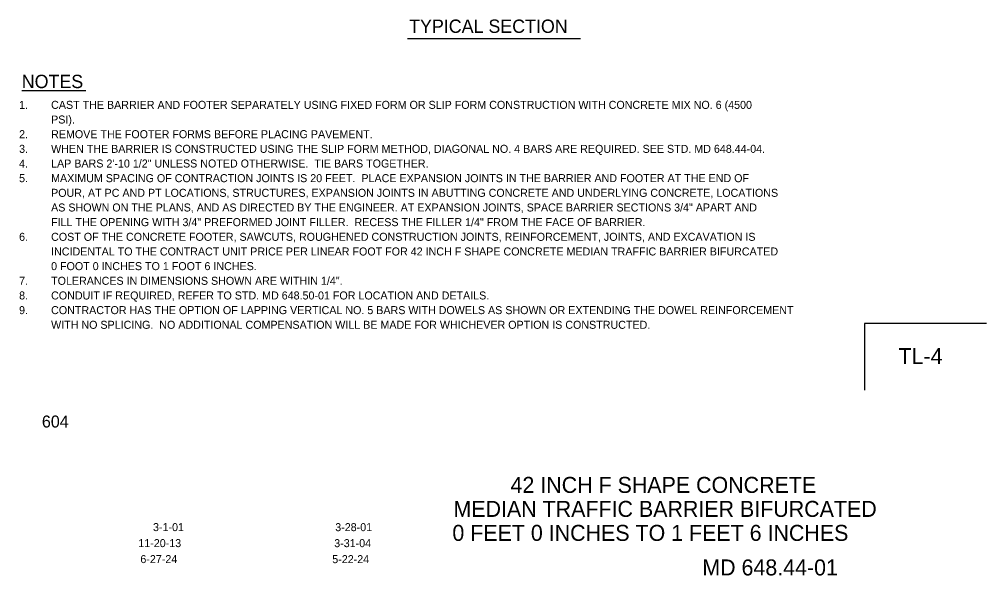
# Model space of a CAD drawing. Extents: x -26.46 to -19.21, y -3.62 to 6.25.
# Drawn here: x -26.46 to -19.21, y -3.62 to 0.55 of the extents above; entities that cross this region are included whole.
import ezdxf

# ---------------------------------------------------------------- set-up
doc = ezdxf.new("R2010")
doc.units = 0
for name, color, linetype in [('Level 1', 7, 'Continuous'), ('Level 12', 7, 'Continuous'), ('Level 13', 7, 'Continuous'), ('TTLB-TEXT', 7, 'Continuous')]:
    doc.layers.add(name, color=color, linetype=linetype)

msp = doc.modelspace()

# ---------------------------------------------------------------- linework, layer by layer
at = {"layer": 'Level 1'}
for p, q in [((-19.2061, -1.7326), (-20.1228, -1.7326)), ((-20.1228, -1.7326), (-20.1228, -2.2326))]:
    msp.add_line(p, q, dxfattribs=at)
at = {"layer": 'Level 12'}
msp.add_line((-23.5481, 0.4063), (-22.2512, 0.4063), dxfattribs=at)
at = {"layer": 'Level 13'}
msp.add_line((-26.4422, 0.0164), (-25.9619, 0.0164), dxfattribs=at)

# ---------------------------------------------------------------- texts
at = {"layer": 'Level 12'}
msp.add_text('TYPICAL SECTION', height=0.1, dxfattribs=at).set_placement((-23.5369, 0.4479))
at = {"layer": 'Level 13'}
for s, height, p in [('NOTES', 0.1, (-26.4421, 0.0334)), ('1.', 0.06, (-26.462, -0.1221)), ('CAST THE BARRIER AND FOOTER SEPARATELY USING FIXED FORM OR SLIP FORM CONSTRUCTION WITH CONCRETE MIX NO. 6 (4500 ', 0.06, (-26.222, -0.1221)), ('PSI).', 0.06, (-26.222, -0.2321)), ('2.', 0.06, (-26.462, -0.3421)), ('REMOVE THE FOOTER FORMS BEFORE PLACING PAVEMENT.', 0.06, (-26.222, -0.3421)), ('3.', 0.06, (-26.462, -0.4521)), ('WHEN THE BARRIER IS CONSTRUCTED USING THE SLIP FORM METHOD, DIAGONAL NO. 4 BARS ARE REQUIRED. SEE STD. MD 648.44-04.', 0.06, (-26.222, -0.4521)), ('4.', 0.06, (-26.462, -0.5621)), ('LAP BARS 2\'-10 1/2" UNLESS NOTED OTHERWISE.  TIE BARS TOGETHER.', 0.06, (-26.222, -0.5621)), ('5.', 0.06, (-26.462, -0.6721)), ('MAXIMUM SPACING OF CONTRACTION JOINTS IS 20 FEET.  PLACE EXPANSION JOINTS IN THE BARRIER AND FOOTER AT THE END OF ', 0.06, (-26.222, -0.6721)), ('POUR, AT PC AND PT LOCATIONS, STRUCTURES, EXPANSION JOINTS IN ABUTTING CONCRETE AND UNDERLYING CONCRETE, LOCATIONS ', 0.06, (-26.222, -0.7821)), ('AS SHOWN ON THE PLANS, AND AS DIRECTED BY THE ENGINEER. AT EXPANSION JOINTS, SPACE BARRIER SECTIONS 3/4" APART AND ', 0.06, (-26.222, -0.8921)), ('FILL THE OPENING WITH 3/4" PREFORMED JOINT FILLER.  RECESS THE FILLER 1/4" FROM THE FACE OF BARRIER.', 0.06, (-26.222, -1.0021)), ('6.', 0.06, (-26.462, -1.1121)), ('COST OF THE CONCRETE FOOTER, SAWCUTS, ROUGHENED CONSTRUCTION JOINTS, REINFORCEMENT, JOINTS, AND EXCAVATION IS ', 0.06, (-26.222, -1.1121)), ('INCIDENTAL TO THE CONTRACT UNIT PRICE PER LINEAR FOOT FOR 42 INCH F SHAPE CONCRETE MEDIAN TRAFFIC BARRIER BIFURCATED ', 0.06, (-26.222, -1.2221)), ('0 FOOT 0 INCHES TO 1 FOOT 6 INCHES.', 0.06, (-26.222, -1.3321)), ('7.', 0.06, (-26.462, -1.4421)), ('TOLERANCES IN DIMENSIONS SHOWN ARE WITHIN 1/4".', 0.06, (-26.222, -1.4421)), ('8.', 0.06, (-26.462, -1.5521)), ('CONDUIT IF REQUIRED, REFER TO STD. MD 648.50-01 FOR LOCATION AND DETAILS.', 0.06, (-26.222, -1.5521)), ('9.', 0.06, (-26.462, -1.6621)), ('CONTRACTOR HAS THE OPTION OF LAPPING VERTICAL NO. 5 BARS WITH DOWELS AS SHOWN OR EXTENDING THE DOWEL REINFORCEMENT ', 0.06, (-26.222, -1.6621)), ('WITH NO SPLICING.  NO ADDITIONAL COMPENSATION WILL BE MADE FOR WHICHEVER OPTION IS CONSTRUCTED.', 0.06, (-26.222, -1.7721)), ('604', 0.09001, (-26.291, -2.5127)), ('42 INCH F SHAPE CONCRETE', 0.120019, (-22.7765, -3.0032)), ('MEDIAN TRAFFIC BARRIER BIFURCATED', 0.120019, (-23.2048, -3.1832)), ('3-1-01', 0.06, (-25.4576, -3.2899)), ('3-28-01', 0.06, (-24.0912, -3.2903)), ('0 FEET 0 INCHES TO 1 FEET 6 INCHES', 0.120019, (-23.2127, -3.3632)), ('11-20-13', 0.06, (-25.5678, -3.4099)), ('3-31-04', 0.06, (-24.0988, -3.4103)), ('6-27-24', 0.06, (-25.5525, -3.5299)), ('5-22-24', 0.06, (-24.1134, -3.5303)), ('MD 648.44-01', 0.12, (-21.3385, -3.6224))]:
    msp.add_text(s, height=height, dxfattribs=at).set_placement(p)
at = {"layer": 'TTLB-TEXT'}
msp.add_text('TL-4', height=0.12, dxfattribs=at).set_placement((-19.8667, -2.0369))

doc.saveas('drawing.dxf')
